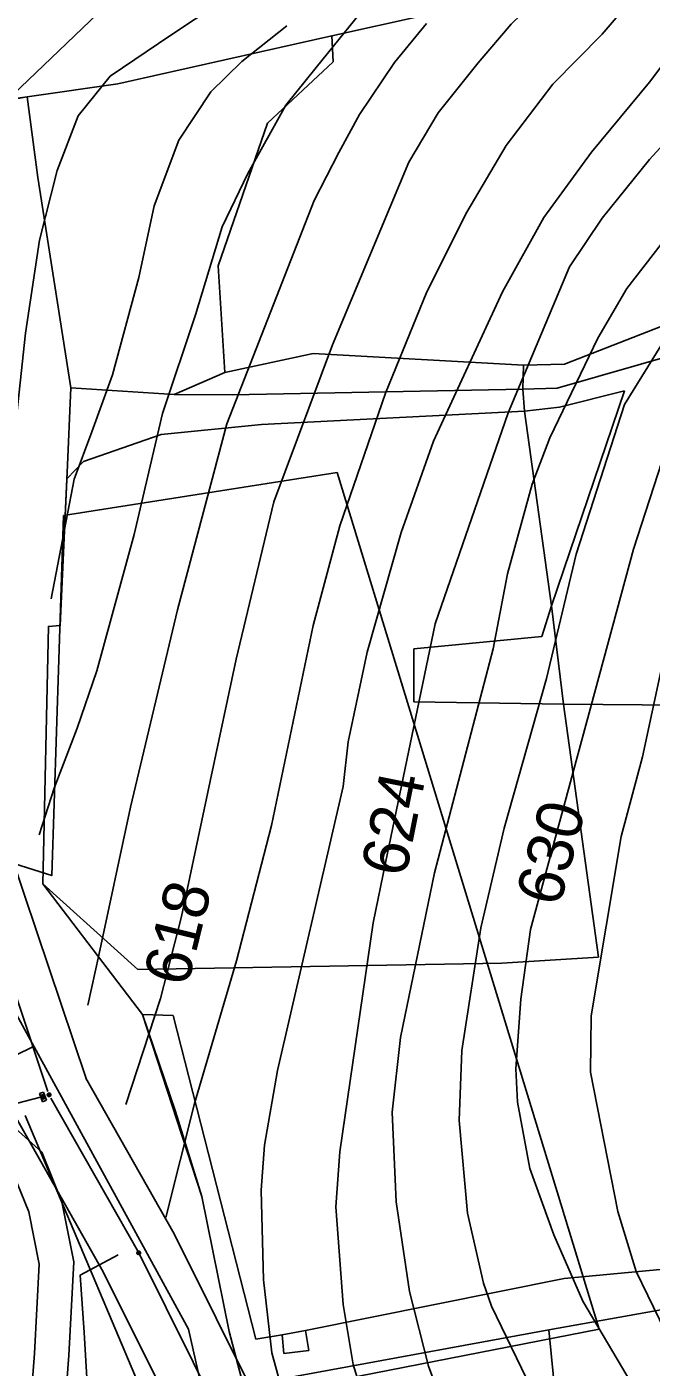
# Model space of a CAD drawing. Extents: x -709418 to -703832, y -1161719 to -1157826.
# Drawn here: x -707032.1 to -706923.2, y -1160213.8 to -1159980.3 of the extents above; entities that cross this region are included whole.
import ezdxf

# ---------------------------------------------------------------- set-up
doc = ezdxf.new("R2010")
doc.units = 0
for name, color, linetype in [('102_obvod PÚ', 7, 'Continuous'), ('106_zastavitelné plochy', 7, 'Continuous'), ('110_silnice II. třídy a III. třídy', 7, 'Continuous'), ('120_vrstevnice hlavní', 7, 'Continuous'), ('121_vrstevnice hlavní_popis', 7, 'Continuous'), ('122_vrstevnice základní', 7, 'Continuous'), ('206_TTP_KN', 7, 'Continuous'), ('207_lesní pozemek_KN', 7, 'Continuous'), ('210_ostatní plocha_KN', 7, 'Continuous'), ('501_vodní tok', 7, 'Continuous'), ('708_el NN nadzemní a podzemní_ E.ON', 7, 'Continuous'), ('735_OP sítí TI', 7, 'Continuous')]:
    doc.layers.add(name, color=color, linetype=linetype)

# ---------------------------------------------------------------- blocks, each defined once
blk = doc.blocks.new('Elektro - Implicitní$0$NN4601')
for points in [[(0.63, 0), (0.62, 0.07), (0.61, 0.13), (0.6, 0.2), (0.57, 0.26), (0.54, 0.32), (0.51, 0.37), (0.47, 0.42), (0.42, 0.47), (0.37, 0.51), (0.31, 0.55), (0.25, 0.58), (0.19, 0.6), (0.13, 0.62), (0.06, 0.63), (0, 0.63), (-0.07, 0.63), (-0.13, 0.62), (-0.2, 0.6), (-0.26, 0.58), (-0.32, 0.55), (-0.37, 0.51), (-0.42, 0.47), (-0.47, 0.42), (-0.51, 0.37), (-0.55, 0.32), (-0.58, 0.26), (-0.6, 0.2), (-0.62, 0.13), (-0.63, 0.07), (-0.63, 0), (-0.63, -0.07), (-0.62, -0.13), (-0.6, -0.19), (-0.58, -0.26), (-0.55, -0.31), (-0.51, -0.37), (-0.47, -0.42), (-0.42, -0.47), (-0.37, -0.51), (-0.32, -0.54), (-0.26, -0.57), (-0.2, -0.6), (-0.13, -0.62), (-0.07, -0.63), (0, -0.63), (0.06, -0.63), (0.13, -0.62), (0.19, -0.6), (0.25, -0.57), (0.31, -0.54), (0.37, -0.51), (0.42, -0.47), (0.47, -0.42), (0.51, -0.37), (0.54, -0.31), (0.57, -0.26), (0.6, -0.19), (0.61, -0.13), (0.62, -0.07), (0.63, 0)], [(0.47, 0), (0.47, 0.05), (0.46, 0.1), (0.45, 0.15), (0.43, 0.19), (0.41, 0.24), (0.38, 0.28), (0.35, 0.32), (0.31, 0.35), (0.28, 0.38), (0.23, 0.41), (0.19, 0.43), (0.14, 0.45), (0.1, 0.46), (0.05, 0.47), (0, 0.47), (-0.05, 0.47), (-0.1, 0.46), (-0.15, 0.45), (-0.19, 0.43), (-0.24, 0.41), (-0.28, 0.38), (-0.32, 0.35), (-0.35, 0.32), (-0.38, 0.28), (-0.41, 0.24), (-0.43, 0.19), (-0.45, 0.15), (-0.46, 0.1), (-0.47, 0.05), (-0.47, 0), (-0.47, -0.05), (-0.46, -0.1), (-0.45, -0.15), (-0.43, -0.19), (-0.41, -0.24), (-0.38, -0.28), (-0.35, -0.32), (-0.32, -0.35), (-0.28, -0.38), (-0.24, -0.41), (-0.19, -0.43), (-0.15, -0.45), (-0.1, -0.46), (-0.05, -0.47), (0, -0.47), (0.05, -0.47), (0.1, -0.46), (0.14, -0.45), (0.19, -0.43), (0.23, -0.41), (0.28, -0.38), (0.31, -0.35), (0.35, -0.32), (0.38, -0.28), (0.41, -0.24), (0.43, -0.19), (0.45, -0.15), (0.46, -0.1), (0.47, -0.05), (0.47, 0)], [(0.31, 0), (0.31, 0.03), (0.31, 0.07), (0.3, 0.1), (0.29, 0.13), (0.27, 0.16), (0.25, 0.19), (0.23, 0.21), (0.21, 0.23), (0.18, 0.26), (0.15, 0.27), (0.13, 0.29), (0.09, 0.3), (0.06, 0.31), (0.03, 0.31), (0, 0.32), (-0.04, 0.31), (-0.07, 0.31), (-0.1, 0.3), (-0.13, 0.29), (-0.16, 0.27), (-0.19, 0.26), (-0.21, 0.23), (-0.24, 0.21), (-0.26, 0.19), (-0.28, 0.16), (-0.29, 0.13), (-0.3, 0.1), (-0.31, 0.07), (-0.32, 0.03), (-0.32, 0), (-0.32, -0.03), (-0.31, -0.06), (-0.3, -0.1), (-0.29, -0.13), (-0.28, -0.16), (-0.26, -0.18), (-0.24, -0.21), (-0.21, -0.23), (-0.19, -0.25), (-0.16, -0.27), (-0.13, -0.29), (-0.1, -0.3), (-0.07, -0.31), (-0.04, -0.31), (0, -0.31), (0.03, -0.31), (0.06, -0.31), (0.09, -0.3), (0.13, -0.29), (0.15, -0.27), (0.18, -0.25), (0.21, -0.23), (0.23, -0.21), (0.25, -0.18), (0.27, -0.16), (0.29, -0.13), (0.3, -0.1), (0.31, -0.06), (0.31, -0.03), (0.31, 0)], [(0.15, 0), (0.15, 0.02), (0.15, 0.03), (0.15, 0.05), (0.14, 0.06), (0.13, 0.08), (0.13, 0.09), (0.11, 0.11), (0.1, 0.12), (0.09, 0.13), (0.08, 0.14), (0.06, 0.14), (0.05, 0.15), (0.03, 0.15), (0.01, 0.16), (0, 0.16), (-0.02, 0.16), (-0.04, 0.15), (-0.05, 0.15), (-0.07, 0.14), (-0.08, 0.14), (-0.09, 0.13), (-0.11, 0.12), (-0.12, 0.11), (-0.13, 0.09), (-0.14, 0.08), (-0.15, 0.06), (-0.15, 0.05), (-0.16, 0.03), (-0.16, 0.02), (-0.16, 0), (-0.16, -0.02), (-0.16, -0.03), (-0.15, -0.05), (-0.15, -0.06), (-0.14, -0.08), (-0.13, -0.09), (-0.12, -0.1), (-0.11, -0.12), (-0.09, -0.13), (-0.08, -0.14), (-0.07, -0.14), (-0.05, -0.15), (-0.04, -0.15), (-0.02, -0.16), (0, -0.16), (0.01, -0.16), (0.03, -0.15), (0.05, -0.15), (0.06, -0.14), (0.08, -0.14), (0.09, -0.13), (0.1, -0.12), (0.11, -0.1), (0.13, -0.09), (0.13, -0.08), (0.14, -0.06), (0.15, -0.05), (0.15, -0.03), (0.15, -0.02), (0.15, 0)]]:
    blk.add_lwpolyline(points)
blk = doc.blocks.new('Elektro - Implicitní$0$NN6201')
for points in [[(0.75, 0), (-0.75, 0)], [(-0.75, 0), (-0.75, -0.75)], [(0.75, -0.75), (0.75, 0)], [(-0.75, -0.75), (0.75, -0.75)], [(0.37, -0.18), (-0.38, -0.18)], [(-0.38, -0.18), (-0.38, -0.56)], [(-0.38, -0.56), (0.37, -0.56)], [(0.32, -0.23), (-0.33, -0.23)], [(-0.33, -0.23), (-0.33, -0.51)], [(-0.33, -0.51), (0.32, -0.51)], [(0.27, -0.27), (-0.28, -0.27)], [(-0.28, -0.27), (-0.28, -0.46)], [(-0.28, -0.46), (0.27, -0.46)], [(0.23, -0.32), (-0.23, -0.32)], [(-0.23, -0.32), (-0.23, -0.42)], [(-0.23, -0.42), (0.23, -0.42)], [(-0.19, -0.37), (0.19, -0.37)], [(0.23, -0.42), (0.23, -0.32)], [(0.27, -0.46), (0.27, -0.27)], [(0.32, -0.51), (0.32, -0.23)], [(0.37, -0.56), (0.37, -0.18)]]:
    blk.add_lwpolyline(points)

msp = doc.modelspace()

# ---------------------------------------------------------------- linework, layer by layer
at = {"layer": '102_obvod PÚ'}
msp.add_lwpolyline([(-706985.28, -1160251.16), (-706996.77, -1160207.56), (-707001.57, -1160184.03), (-707011.88, -1160152.35), (-707029.26, -1160129.55), (-707028.31, -1160084.72), (-707026.24, -1160084.58), (-707025.05, -1160057.91), (-707024.39, -1160043.15), (-707030.12, -1160006.54), (-707032.01, -1159992.48), (-707080.89, -1160001.26)], dxfattribs=at)
at = {"layer": '106_zastavitelné plochy'}
msp.add_lwpolyline([(-706977.94, -1160057.93), (-706932.26, -1160207.16), (-706994.98, -1160219.43), (-706984.08, -1160254.18), (-706992.94, -1160255.55), (-707003.85, -1160207.16), (-707035.21, -1160149.92), (-707038.62, -1160124.71), (-707027.71, -1160128.12), (-707025.66, -1160065.42), (-706977.94, -1160057.93)], dxfattribs=at)
at = {"layer": '110_silnice II. třídy a III. třídy'}
msp.add_lwpolyline([(-707032.37, -1160169.9), (-707002, -1160241.7), (-706986.57, -1160329.88), (-706984.16, -1160358.65), (-706995.74, -1160401.05), (-707031.42, -1160441.53), (-707063.24, -1160500.31)], dxfattribs=at)
at = {"layer": '120_vrstevnice hlavní'}
for points in [[(-707017.53, -1159988.85), (-707006.97, -1159981.72), (-706998.55, -1159976.16), (-706991.45, -1159969.75), (-706987.2, -1159963.63), (-706983.84, -1159955.83), (-706980.37, -1159945.41), (-706978.06, -1159935), (-706975.47, -1159923.3), (-706974.01, -1159913.97)], [(-706850.08, -1159968), (-706864.28, -1159986.25), (-706881.72, -1160002.84), (-706892.86, -1160013.54), (-706901.83, -1160023.23), (-706910.65, -1160034.37), (-706914.99, -1160040.88), (-706920.63, -1160053.9), (-706926.28, -1160071.26), (-706944.21, -1160137.5), (-706945.95, -1160149.65), (-706946.82, -1160161.8), (-706946.53, -1160167.59), (-706944.36, -1160179.16), (-706940.16, -1160190.73), (-706935.1, -1160202.3), (-706924.83, -1160219.66)], [(-706927.19, -1159976.29), (-706931.75, -1159981.56), (-706940.36, -1159990.26), (-706948.49, -1160000.97), (-706955.35, -1160012.53), (-706962.29, -1160026.42), (-706969.52, -1160044.06), (-706977.48, -1160067.21), (-706982.11, -1160084.56), (-706989.4, -1160119.38), (-706995.5, -1160142.99), (-707002.82, -1160167.85), (-707007.82, -1160187.71)], [(-707034.75, -1160086.95), (-707034.45, -1160074.64), (-707034.9, -1160057.95), (-707032.3, -1160033.65), (-707029.84, -1160017.45), (-707026.8, -1160005.3), (-707023.14, -1159995.79), (-707017.53, -1159988.85)]]:
    msp.add_lwpolyline(points, dxfattribs=at)
at = {"layer": '122_vrstevnice základní'}
for points in [[(-706981.63, -1159987.33), (-706970.95, -1159974.19), (-706961.29, -1159962.65), (-706954.83, -1159953.4), (-706950.88, -1159944.61), (-706948.26, -1159935.64), (-706942.66, -1159918.05), (-706937.79, -1159902.61)], [(-707041.27, -1159998.5), (-707009.01, -1159967.69), (-707002.07, -1159957.28), (-706995.42, -1159941.65), (-706991.94, -1159928.64), (-706991.08, -1159921.84), (-706975.74, -1159906.51)], [(-706848.67, -1159942.59), (-706855.83, -1159954.29), (-706864.75, -1159968.89), (-706873.9, -1159980.95), (-706886.33, -1159995.04), (-706902.24, -1160010.83), (-706914.42, -1160024.39), (-706927.87, -1160046.09), (-706936.26, -1160072.12), (-706941.46, -1160093.82), (-706948.84, -1160119.85), (-706952.89, -1160137.21), (-706956.22, -1160158.62), (-706956.65, -1160170.77), (-706955.21, -1160186.97), (-706952.46, -1160199.12), (-706951.01, -1160203.17), (-706943.2, -1160219.37)], [(-706959.11, -1160221.4), (-706962, -1160213.58), (-706965.33, -1160200.57), (-706967.64, -1160184.95), (-706968.37, -1160169.32), (-706966.92, -1160156.31), (-706960.99, -1160127.67), (-706950.72, -1160088.61), (-706948.26, -1160075.59), (-706943.92, -1160059.97), (-706940.88, -1160051.87), (-706932.49, -1160034.52), (-706927.43, -1160025.84), (-706886.93, -1159973.54), (-706878.46, -1159961.35), (-706872.34, -1159951.47)], [(-706984.57, -1160228.63), (-706989.34, -1160211.27), (-706990.79, -1160198.54), (-706991.22, -1160182.92), (-706990.64, -1160175.11), (-706988.33, -1160162.09), (-706976.9, -1160112.62), (-706976.03, -1160104.81), (-706972.71, -1160089.19), (-706966.78, -1160068.36), (-706961.14, -1160052.45), (-706949.13, -1160026.42), (-706941.92, -1160013.46), (-706933.62, -1160002.09), (-706923.47, -1159989.92), (-706906, -1159966.65), (-706899.72, -1159957.09)], [(-706892.81, -1159962.06), (-706903.5, -1159978.38), (-706915.53, -1159994.68), (-706923.46, -1160003.38), (-706931.74, -1160013.58), (-706937.41, -1160022.08), (-706948.12, -1160047.53), (-706960.85, -1160084.27), (-706969.52, -1160125.93), (-706971.69, -1160136.34), (-706977.48, -1160176.27), (-706978.2, -1160185.81), (-706976.9, -1160202.88), (-706975.17, -1160213.3), (-706969.81, -1160230.65)], [(-706940.69, -1159973.06), (-706947.61, -1159979.79), (-706953.37, -1159986.54), (-706960.31, -1159995.28), (-706965.47, -1160003.85), (-706978.78, -1160035.67), (-706989.02, -1160063.02), (-706995.55, -1160090.41), (-707000.1, -1160111.69), (-707005.08, -1160135.27), (-707008.77, -1160149.54), (-707014.8, -1160168.02)], [(-707027.82, -1160079.94), (-707023.78, -1160059.09), (-707020.74, -1160050.84), (-707017.1, -1160040.88), (-707012.54, -1160023.93), (-707009.87, -1160011.45), (-707005.58, -1160000.01), (-706999.96, -1159991.57), (-706994.57, -1159986.33), (-706986.73, -1159980.1)], [(-707021.41, -1160150.73), (-707019.5, -1160141.97), (-707013.99, -1160116.21), (-707005.79, -1160081.83), (-706997.19, -1160049.45), (-706981.96, -1160010.5), (-706977.66, -1160002.17), (-706974.07, -1159995.55), (-706967.95, -1159986.47), (-706962.36, -1159979.71)], [(-706981.63, -1159987.33), (-706986.89, -1159993.93), (-706993.55, -1160005.84), (-706998.01, -1160015.12), (-707002.65, -1160030.47), (-707008.38, -1160047.62), (-707013.34, -1160068.73), (-707019.83, -1160092.48), (-707023.29, -1160102.44), (-707027.27, -1160112.89), (-707029.92, -1160121.02)], [(-706901.94, -1160034.93), (-706909.64, -1160050.57), (-706911.67, -1160055.92), (-706919.48, -1160083.12), (-706924.69, -1160107.42), (-706928.45, -1160121.3), (-706933.65, -1160152.55), (-706933.8, -1160162.38), (-706929.02, -1160186.68), (-706925.84, -1160197.09), (-706920.78, -1160207.51), (-706914.27, -1160217.78)], [(-707178.54, -1160122.31), (-707166.39, -1160129.84), (-707155.68, -1160135.48), (-707144.98, -1160139.67), (-707136.88, -1160141.84), (-707120.68, -1160144.45), (-707107.95, -1160149.8), (-707096.23, -1160157.75), (-707064.89, -1160183.61), (-707057.44, -1160187.88), (-707050.94, -1160188.3), (-707045.92, -1160187.2), (-707042.22, -1160184.58), (-707039.34, -1160181.12), (-707038.1, -1160175.96), (-707037.5, -1160168.63), (-707037.81, -1160161.26), (-707030.76, -1160157.83)], [(-707032.82, -1160228.1), (-707029, -1160229.65), (-707025.84, -1160229.86), (-707023.66, -1160228.89), (-707021.94, -1160225.24), (-707021.5, -1160217.58), (-707022.04, -1160207.74), (-707022.74, -1160197.72), (-707016.12, -1160194.18)]]:
    msp.add_lwpolyline(points, dxfattribs=at)
at = {"layer": '206_TTP_KN'}
for p, q in [((-706963.1, -1159978.33), (-706978.89, -1159981.86)), ((-706978.89, -1159981.86), (-706963.1, -1159978.33)), ((-706978.89, -1159981.86), (-707016.19, -1159990.18)), ((-707016.19, -1159990.18), (-706978.89, -1159981.86)), ((-706978.89, -1159981.86), (-706978.62, -1159986.36)), ((-706978.62, -1159986.36), (-706978.89, -1159981.86)), ((-706978.62, -1159986.36), (-706990.07, -1159997.07)), ((-706990.07, -1159997.07), (-706978.62, -1159986.36)), ((-707016.19, -1159990.18), (-707032.01, -1159992.48)), ((-707032.01, -1159992.48), (-707016.19, -1159990.18)), ((-707032.01, -1159992.48), (-707047.56, -1159994.66)), ((-707030.12, -1160006.54), (-707032.01, -1159992.48)), ((-706990.07, -1159997.07), (-706998.69, -1160021.92)), ((-706998.69, -1160021.92), (-706990.07, -1159997.07)), ((-707024.39, -1160043.15), (-707030.12, -1160006.54)), ((-706888.24, -1160019.42), (-706938.32, -1160039.05)), ((-706998.69, -1160021.92), (-706997.55, -1160040.47)), ((-706997.55, -1160040.47), (-706998.69, -1160021.92)), ((-706982.14, -1160037.19), (-706997.55, -1160040.47)), ((-706945.46, -1160039.19), (-706982.14, -1160037.19)), ((-706938.32, -1160039.05), (-706945.46, -1160039.19)), ((-706997.55, -1160040.47), (-707006.4, -1160044.33)), ((-707006.4, -1160044.33), (-707024.39, -1160043.15)), ((-706927.85, -1160043.66), (-706940.57, -1160081.13)), ((-706939.2, -1160046.51), (-706927.85, -1160043.66)), ((-706991.16, -1160049.52), (-706945.28, -1160047.2)), ((-706945.28, -1160047.2), (-706939.2, -1160046.51)), ((-706945.28, -1160047.2), (-706940.57, -1160081.13)), ((-706940.57, -1160081.13), (-706945.28, -1160047.2)), ((-707008.63, -1160051.28), (-706991.16, -1160049.52)), ((-707022.2, -1160055.98), (-707008.63, -1160051.28)), ((-707025.1, -1160059.01), (-707022.2, -1160055.98)), ((-707026.24, -1160084.58), (-707025.1, -1160059.01)), ((-706940.57, -1160081.13), (-706942.28, -1160086.48)), ((-707029.26, -1160129.55), (-707028.31, -1160084.72)), ((-707028.31, -1160084.72), (-707026.24, -1160084.58)), ((-706942.28, -1160086.48), (-706964.58, -1160088.62)), ((-706964.58, -1160088.62), (-706964.58, -1160097.86)), ((-706964.58, -1160097.86), (-706938.5, -1160098.26)), ((-706938.5, -1160098.26), (-706932.38, -1160142.37)), ((-706932.38, -1160142.37), (-706938.5, -1160098.26)), ((-706938.5, -1160098.26), (-706896.55, -1160098.66)), ((-707012.73, -1160144.51), (-707029.26, -1160129.55)), ((-707029.26, -1160129.55), (-707012.73, -1160144.51)), ((-707011.88, -1160152.35), (-707029.26, -1160129.55)), ((-706949.22, -1160143.37), (-707012.73, -1160144.51)), ((-707012.73, -1160144.51), (-706949.22, -1160143.37)), ((-706932.38, -1160142.37), (-706949.22, -1160143.37)), ((-706949.22, -1160143.37), (-706932.38, -1160142.37)), ((-707006.52, -1160152.48), (-707011.88, -1160152.35)), ((-706992.16, -1160208.91), (-707006.52, -1160152.48)), ((-706839.74, -1160188.93), (-706938.37, -1160198.33)), ((-706938.37, -1160198.33), (-706983.49, -1160207.38)), ((-706990.73, -1160216.4), (-706941.07, -1160207.27)), ((-706983.49, -1160207.38), (-706987.56, -1160208.16)), ((-706941.07, -1160207.27), (-706937.25, -1160245.26)), ((-706987.56, -1160208.16), (-706992.16, -1160208.91))]:
    msp.add_line(p, q, dxfattribs=at)
at = {"layer": '207_lesní pozemek_KN'}
for p, q in [((-706941.07, -1160207.27), (-706895.68, -1160199.2)), ((-706937.25, -1160245.26), (-706941.07, -1160207.27))]:
    msp.add_line(p, q, dxfattribs=at)
at = {"layer": '210_ostatní plocha_KN'}
for p, q in [((-706938.32, -1160039.05), (-706888.24, -1160019.42)), ((-706911.45, -1160035.14), (-706939.61, -1160043.24)), ((-706939.61, -1160043.24), (-706911.45, -1160035.14)), ((-706997.55, -1160040.47), (-706982.14, -1160037.19)), ((-706982.14, -1160037.19), (-706945.46, -1160039.19)), ((-706945.46, -1160039.19), (-706945.6, -1160043.38)), ((-706945.6, -1160043.38), (-706945.46, -1160039.19)), ((-706945.46, -1160039.19), (-706938.32, -1160039.05)), ((-707006.4, -1160044.33), (-706997.55, -1160040.47)), ((-707025.05, -1160057.91), (-707024.39, -1160043.15)), ((-707024.39, -1160043.15), (-707006.4, -1160044.33)), ((-706996.26, -1160044.38), (-706945.6, -1160043.38)), ((-706945.6, -1160043.38), (-706996.26, -1160044.38)), ((-706939.61, -1160043.24), (-706945.6, -1160043.38)), ((-706945.6, -1160043.38), (-706939.61, -1160043.24)), ((-706945.6, -1160043.38), (-706945.28, -1160047.2)), ((-706945.28, -1160047.2), (-706945.6, -1160043.38)), ((-706940.57, -1160081.13), (-706927.85, -1160043.66)), ((-706927.85, -1160043.66), (-706939.2, -1160046.51)), ((-707006.4, -1160044.33), (-706996.26, -1160044.38)), ((-706996.26, -1160044.38), (-707006.4, -1160044.33)), ((-706945.28, -1160047.2), (-706991.16, -1160049.52)), ((-706939.2, -1160046.51), (-706945.28, -1160047.2)), ((-706991.16, -1160049.52), (-707008.63, -1160051.28)), ((-707008.63, -1160051.28), (-707022.2, -1160055.98)), ((-707022.2, -1160055.98), (-707025.1, -1160059.01)), ((-707025.1, -1160059.01), (-707025.05, -1160057.91)), ((-706942.28, -1160086.48), (-706940.57, -1160081.13)), ((-706940.57, -1160081.13), (-706938.5, -1160098.26)), ((-706938.5, -1160098.26), (-706940.57, -1160081.13)), ((-706964.58, -1160088.62), (-706942.28, -1160086.48)), ((-706964.58, -1160097.86), (-706964.58, -1160088.62)), ((-706938.5, -1160098.26), (-706964.58, -1160097.86)), ((-706896.55, -1160098.66), (-706938.5, -1160098.26)), ((-707011.88, -1160152.35), (-707006.52, -1160152.48)), ((-707006.15, -1160169.21), (-707011.88, -1160152.35)), ((-707006.52, -1160152.48), (-706992.16, -1160208.91)), ((-707001.57, -1160184.03), (-707006.15, -1160169.21)), ((-706996.77, -1160207.56), (-707001.57, -1160184.03)), ((-706938.37, -1160198.33), (-706839.74, -1160188.93)), ((-706983.49, -1160207.38), (-706938.37, -1160198.33)), ((-706895.68, -1160199.2), (-706941.07, -1160207.27)), ((-706941.07, -1160207.27), (-706990.73, -1160216.4)), ((-706987.56, -1160208.16), (-706983.49, -1160207.38)), ((-706982.91, -1160210.86), (-706983.49, -1160207.38)), ((-706983.49, -1160207.38), (-706982.91, -1160210.86)), ((-706985.28, -1160251.16), (-706996.77, -1160207.56)), ((-706992.16, -1160208.91), (-706987.56, -1160208.16)), ((-706987.56, -1160208.16), (-706987.23, -1160211.38)), ((-706987.23, -1160211.38), (-706987.56, -1160208.16)), ((-706987.23, -1160211.38), (-706982.91, -1160210.86)), ((-706982.91, -1160210.86), (-706987.23, -1160211.38))]:
    msp.add_line(p, q, dxfattribs=at)
at = {"layer": '501_vodní tok'}
msp.add_lwpolyline([(-707032.59, -1160235.58), (-707030.74, -1160211.37), (-707029.9, -1160195.84), (-707031.74, -1160186.69), (-707034.48, -1160179.84)], dxfattribs=at)
at = {"layer": '708_el NN nadzemní a podzemní_ E.ON'}
for points in [[(-707028.38, -1160165.73), (-707039.14, -1160133.6), (-707051.07, -1160097.96), (-707063, -1160062.32), (-707069.99, -1160037.73), (-707078.89, -1160008.23)], [(-707029.46, -1160166.66), (-707052.1, -1160172.53)], [(-706987.62, -1160257.8), (-706998.27, -1160222.49), (-707012.55, -1160193.86), (-707027.86, -1160166.88)]]:
    msp.add_lwpolyline(points, dxfattribs=at)
at = {"layer": '735_OP sítí TI'}
for points in [[(-707021.74, -1160163.5), (-707032.5, -1160131.38), (-707044.43, -1160095.74), (-707056.31, -1160060.25), (-707063.27, -1160035.76), (-707072.19, -1160006.21)], [(-706980.92, -1160255.78), (-706991.74, -1160219.9), (-707006.37, -1160190.57), (-707021.78, -1160163.43)], [(-707026.5, -1160234.68), (-707024.76, -1160211.76), (-707023.87, -1160195.41), (-707025.96, -1160184.97), (-707029.43, -1160176.29), (-707037.61, -1160169.03)], [(-706994.32, -1160259.82), (-707004.8, -1160225.08), (-707018.73, -1160197.15), (-707033.95, -1160170.34)]]:
    msp.add_lwpolyline(points, dxfattribs=at)

# ---------------------------------------------------------------- block references
at = {"layer": '708_el NN nadzemní a podzemní_ E.ON', "rotation": -71.07999992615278}
msp.add_blockref('Elektro - Implicitní$0$NN6201', (-707028.89, -1160166.57), dxfattribs=at)
at = {"layer": '708_el NN nadzemní a podzemní_ E.ON'}
for p, xscale, yscale, rotation in [((-707028.18, -1160166.33), 0.49999999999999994, 0.4999999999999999, -61.96095820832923), ((-707012.55, -1160193.86), 0.5, 0.5, -63.491027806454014)]:
    msp.add_blockref('Elektro - Implicitní$0$NN4601', p, dxfattribs=dict(at, xscale=xscale, yscale=yscale, rotation=rotation))

# ---------------------------------------------------------------- texts
at = {"layer": '121_vrstevnice hlavní_popis'}
for s, rotation, p in [('624', 78.6827, (-706966.03, -1160128.61)), ('630', 74.9914, (-706939.2, -1160133.78)), ('618', 76.1186, (-707004.07, -1160147.71))]:
    msp.add_text(s, height=8, rotation=rotation, dxfattribs=at).set_placement(p)

doc.saveas('drawing.dxf')
